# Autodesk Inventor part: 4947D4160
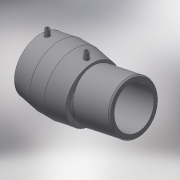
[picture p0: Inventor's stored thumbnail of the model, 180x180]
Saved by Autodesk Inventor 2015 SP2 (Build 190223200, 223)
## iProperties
Created: 2017-06
Part Number: 4947D4160
Material: Generic
Description: PLASSON ADJUSTABLE ELBOW (ONE SIDE) 160
Document SubType Name: Modeling
Designer: KIM
Mass: 4294.79 g
Surface Area: 3830.75 cm^2
Volume: 4294.79 cm^3
Density: 1 g/cm^3
Appearance: Default
Author: KIM
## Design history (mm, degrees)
derived "4947D4.ipt"
feature "Solid1::4947D4.ipt"
tag "TaggingFeature1"
body "Solid1"
other parameters: "d0" = 179.025, "d2" = 215, "d3" = 97, "d4" = 48.5, "d5" = 193.5, "d8" = 168 deg, "d10" = 38.8, "d11" = 12.93333, "d29" = 106, "d30" = 15, "d31" = 68.2, "d34" = 5 deg, "d41" = 4, "d42" = 14, "d43" = 0, "d48" = 144, "d55" = 49.215, "d57" = 168 deg, "d62" = 3, "d63" = 0, "d65" = 341, "d67" = 144, "d68" = 135 deg, "d70" = 79.55, "d71" = 4.3, "L_" = 341, "L_1" = 97, "D_" = 215, "A_" = 106, "d_2" = 12, "L_0" = 148, "d54" = 82.025, "d59" = 211.69827
